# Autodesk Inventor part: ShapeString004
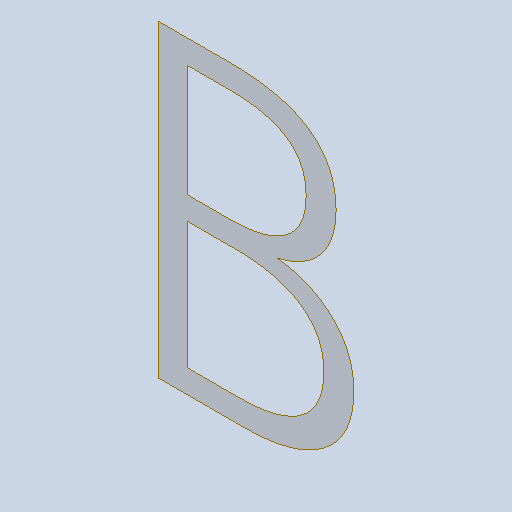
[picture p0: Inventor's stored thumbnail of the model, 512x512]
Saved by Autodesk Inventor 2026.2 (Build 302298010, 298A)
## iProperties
Created: 2026-10
Part Number: ShapeString004
Material: Générique
Document SubType Name: Modeling
Designer: mel
Density: 1 g/cm^3
Appearance: Par défaut
Author: mel
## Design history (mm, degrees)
feature "Composite1"
body "Srf1"
